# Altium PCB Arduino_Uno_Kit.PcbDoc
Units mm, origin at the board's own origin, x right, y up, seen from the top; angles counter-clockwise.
Board outline 142.1 x 65.4 mm, 2 copper layers (TOP, BOTTOM), stack 1.6 mm thick; 43 components, 40 nets, 248 pads, 2 vias.
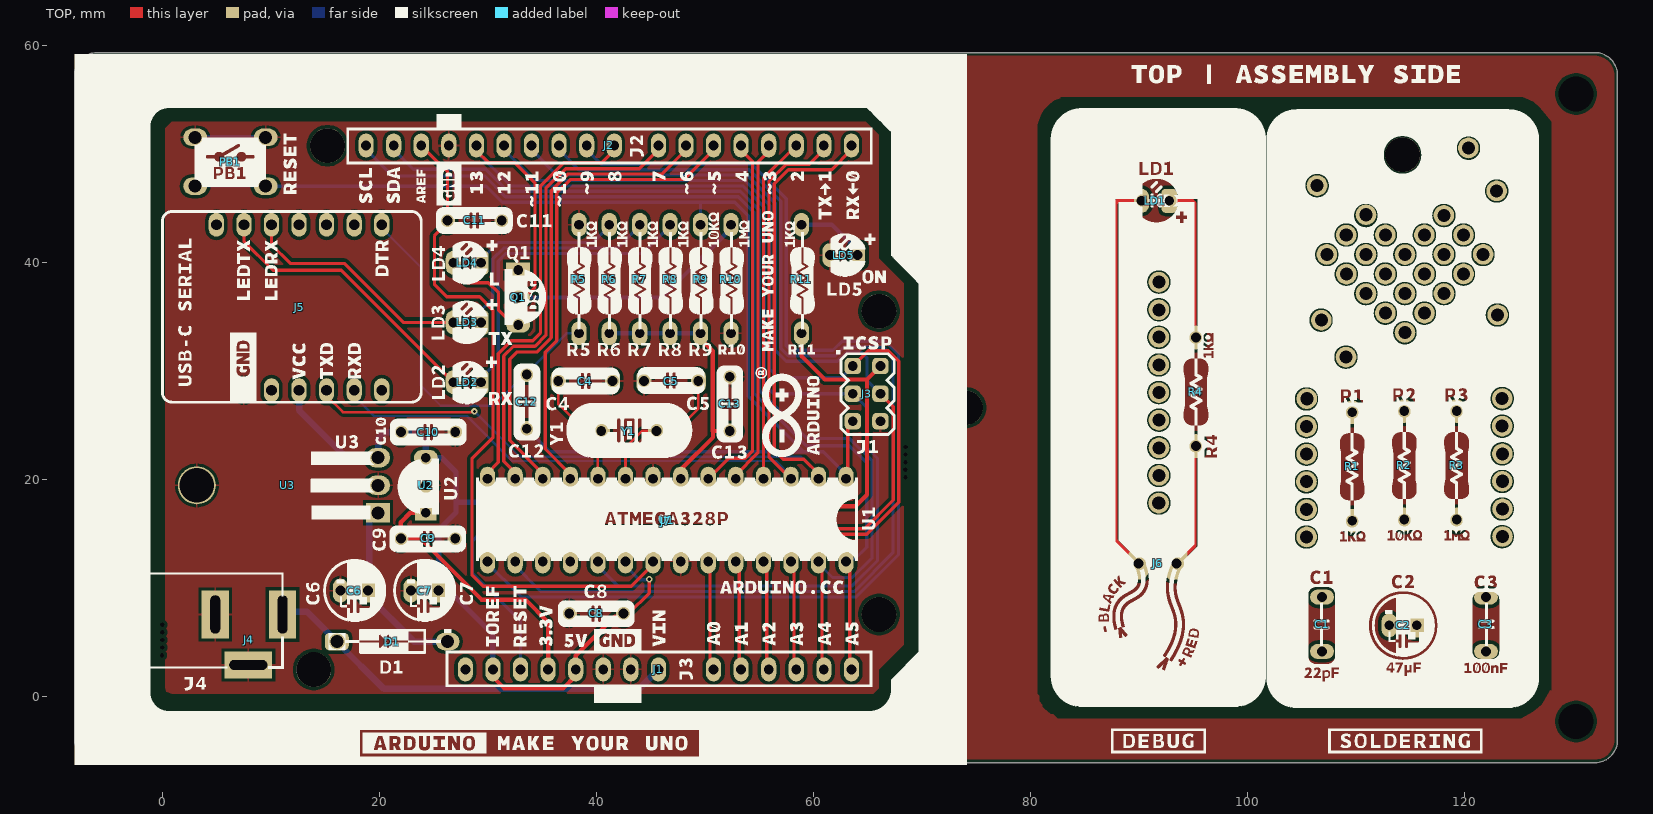
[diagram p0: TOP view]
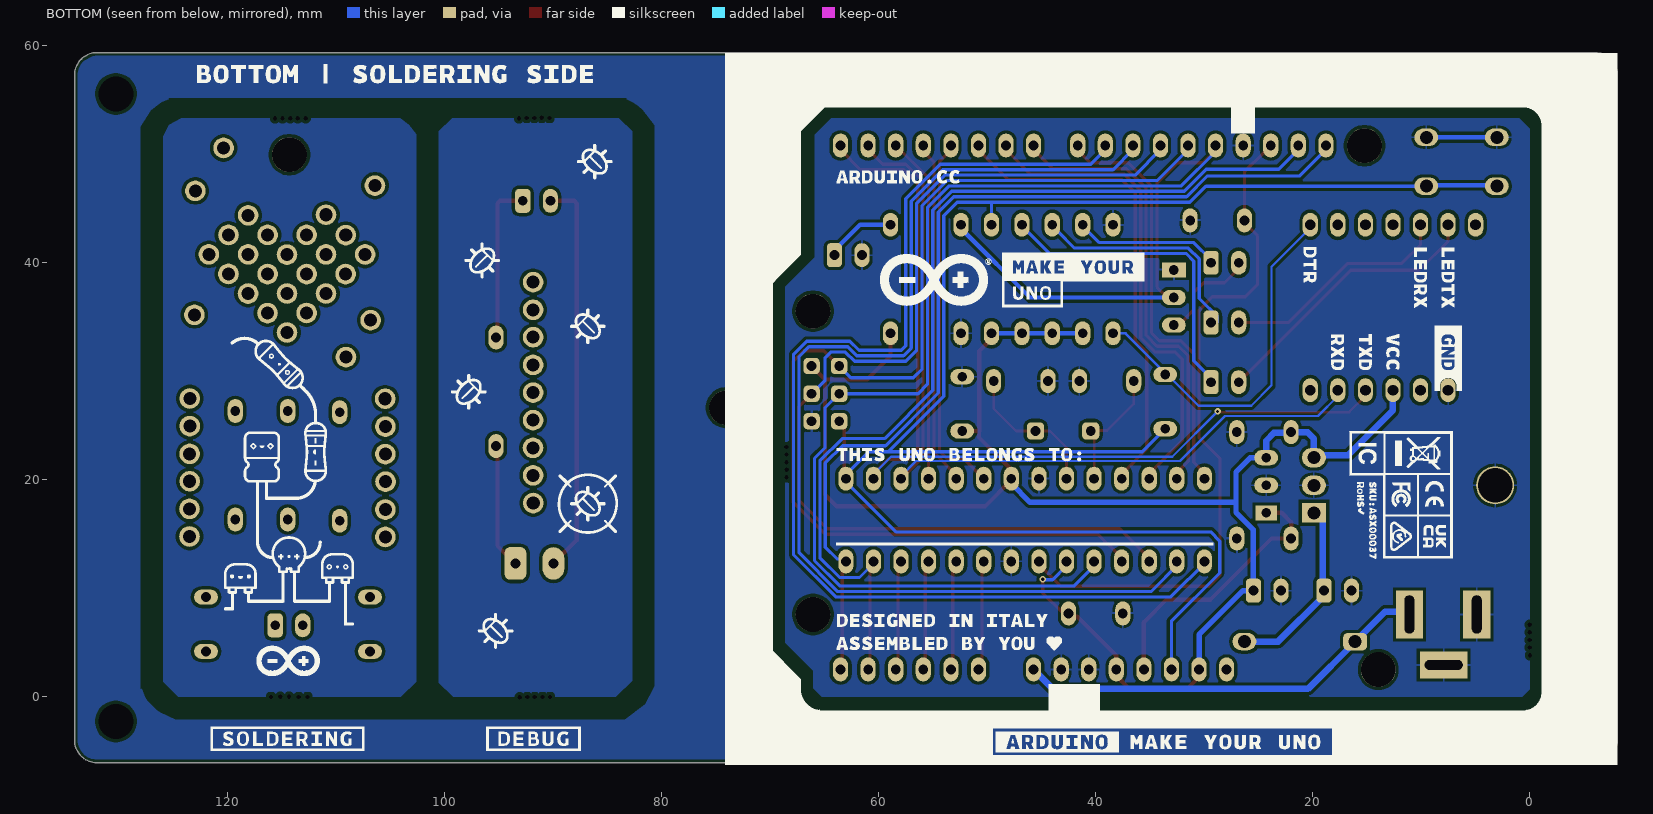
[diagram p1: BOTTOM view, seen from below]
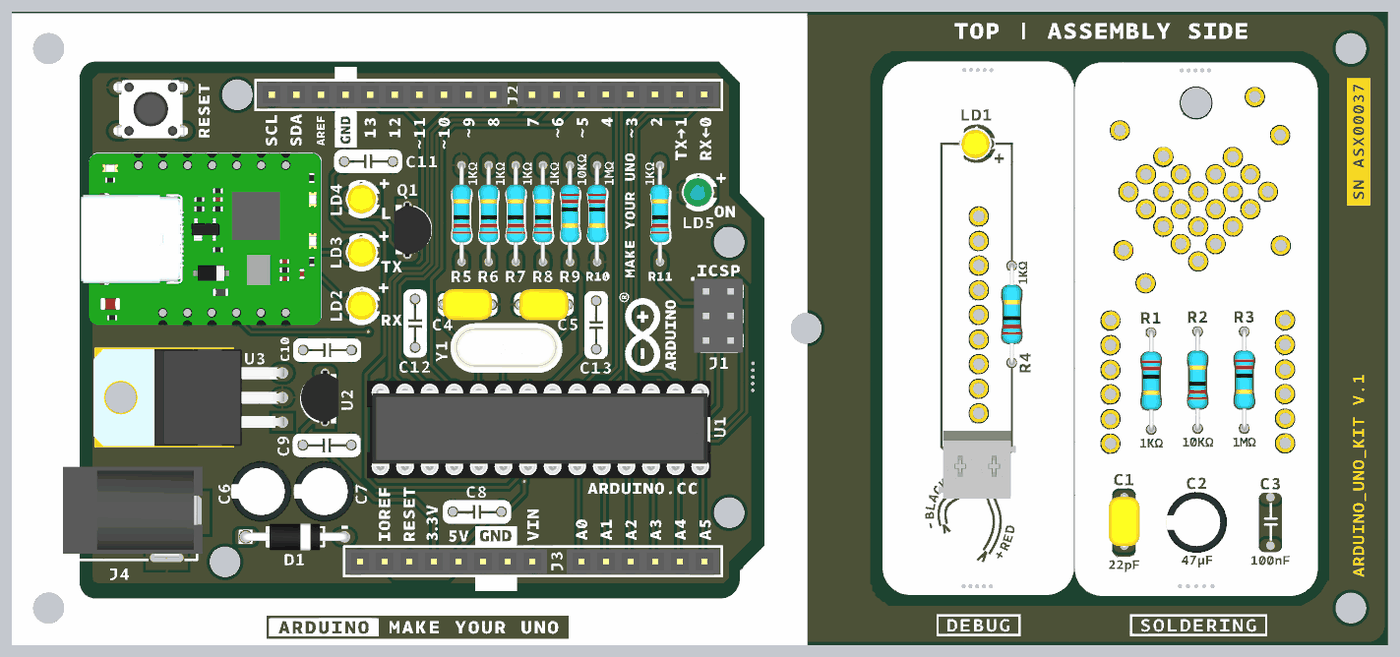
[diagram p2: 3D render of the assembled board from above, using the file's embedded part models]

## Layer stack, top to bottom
Top Solder: solder mask 0.0102, Solder Resist, Dk 3.5
TOP: signal copper 0.018
Dielectric2: core 1.564, FR-4, Dk 4.8
BOTTOM: signal copper 0.018
Bottom Solder: solder mask 0.0102, Solder Resist, Dk 3.5

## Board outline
-8.05,-3.999 -8.05,57.266 -8.05,57.3 cw(c-6,57.3) -6.02,59.35 -6.017,59.35 131.983,59.35 132,59.35 cw(c132,57.3) 134.05,57.3 134.05,-3.996 134.05,-4 cw(c132,-4) 132.029,-6.05 131.999,-6.05 -6,-6.05 cw(c-6,-4)

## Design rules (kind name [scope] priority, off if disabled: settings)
BoardOutlineClearance Silks [(OnLayer('Top Overlay') OR OnLayer('Bottom Overlay'))] p1: gap=0.1 ignorepadtopadclearanceinfootprint=FALSE
BoardOutlineClearance [All] p2: gap=0.3 ignorepadtopadclearanceinfootprint=FALSE
Clearance COPPER_0.3mm [All] p1: gap=0.127 ignorepadtopadclearanceinfootprint=FALSE except(0.2: Arc-Arc Arc-Track Track-Track; 0.3: Arc-Fill Arc-Poly Arc-Region Track-Fill Track-Poly Track-Region SMDPad-Fill SMDPad-Poly SMDPad-Region THPad-Fill THPad-Poly THPad-Region Via-Fill Via-Poly Via-Region Fill-Fill Fill-Poly Fill-Region Poly-Poly Poly-Region Region-Region)
Clearance "Generic clearance 0.127mm" [All] p2: gap=0.127 ignorepadtopadclearanceinfootprint=FALSE except(0.2: Arc-Arc Arc-Track Track-Track)
ComponentClearance [All] p1: gap=0.2 collisioncheckmode=3 verticalgap=0 showdistances=TRUE
DiffPairsRouting USB [InDifferentialPairClass('USB')] p1: maxlimit=0.15 minlimit=0.15 mostfreqgap=0.15 toplayer_minwidth=0.15 toplayer_maxwidth=0.21 toplayer_prefwidth=0.2 bottomlayer_minwidth=0.15 bottomlayer_maxwidth=0.21 bottomlayer_prefwidth=0.2 impedanceprofiledriven=TRUE impedanceprofileid={E6B00C31-4C8E-439C-824F-D2B2CDC26F9C} impedanceprofilevalue=90.000000 maxuncoupledlength=12.7
Height [All] p1: minheight=0 maxheight=30 prefheight=12.7
HoleSize [All] p1: absolutevalues=TRUE maxlimit=20 minlimit=0.3 maxpercent=80.000 minpercent=20.000
HoleToHoleClearance [All] p1: gap=0.2 allowstackedmicrovias=FALSE
MinimumAnnularRing [All] p1: minimumring=0.1
MinimumSolderMaskSliver [All] p1: minsoldermaskwidth=0.1
PlaneConnect [All] p1: pad.planeconnectstyle=Relief pad.reliefexpansion=0.508 pad.reliefentries=4 pad.reliefconductorwidth=0.254 pad.reliefairgap=0.254 via.planeconnectstyle=Direct via.reliefexpansion=0.508 via.reliefentries=4 via.reliefconductorwidth=0.254 via.reliefairgap=0.254
PolygonConnect [All] p1: thpad.connectstyle=Relief thpad.reliefconductorwidth=0.2 thpad.reliefentries=4 thpad.polygonreliefangle="90 Angle" thpad.airgapwidth=0.254 smdpad.connectstyle=Relief smdpad.reliefconductorwidth=0.2 smdpad.reliefentries=4 smdpad.polygonreliefangle="90 Angle" smdpad.airgapwidth=0.254 via.connectstyle=Direct via.reliefconductorwidth=0.254 via.reliefentries=4 via.polygonreliefangle="90 Angle" via.airgapwidth=0.254
RoomDefinition Aruino_Uno_Kit [InComponentClass('Aruino_Uno_Kit')] p1: confinementstyle=ConfineIn formatcopy=TRUE lockcomponents=FALSE outline -13.1,-11.6 148.5,-11.6 148.5,60.5 -13.1,60.5
RoutingVias StandardVias [All] p1: holewidth=0.3 width=0.6 viastyle="Through Hole" minholewidth=0.3 minwidth=0.6 maxholewidth=0.3 maxwidth=0.6
SMDToCorner [All] p1: distance=39370
SilkToSilkClearance [All] p1: silktosilkclearance=0.15
SilkToSolderMaskClearance [IsPad] p1: minsilkscreentomaskgap=0.1 clearancetoexposedcopper=TRUE
SolderMaskExpansion VIAtented [IsVia] p1: expansion=0.102 istentingtop=TRUE
SolderMaskExpansion [All] p2: expansion=0.05 istentingtop=FALSE
UnRoutedNet [All] p1: checkbadconnections=TRUE
ViasUnderSMD [All] p1: allowed=FALSE
Width StandardTraces [All] p1: maxlimit=5 minlimit=0.127 preferedwidth=0.4
20 further rules are at their usual default settings.

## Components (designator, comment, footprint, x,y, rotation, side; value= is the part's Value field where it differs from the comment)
C1 "TS170R1H220JSANB0R" TS170R1H220JSANB0R 106.85,6.7 r90 top value=22pF
C2 "EKF476M1EE05TU" EKF476M1EE05TU 114.307,6.597 r0 top value=47µF
C3 "B32529C0104J289" B32529C0104J289 121.947,6.7 r90 top value=100nF
C4 "TS170R1H220JSANB0R" TS170R1H220JSANB0R 39,29.1 r0 top value=22pF
C5 "TS170R1H220JSANB0R" TS170R1H220JSANB0R 46.9,29.1 r180 top value=22pF
C6 "EKF476M1EE05TU" EKF476M1EE05TU 17.7,9.8 r0 top value=47µF
C7 "EKF476M1EE05TU" EKF476M1EE05TU 24.2,9.8 r0 top value=47µF
C8 "B32529C0104J289" B32529C0104J289 40,7.7 r180 top value=100nF
C9 "B32529C0104J289" B32529C0104J289 24.5,14.6 r0 top value=100nF
C10 "B32529C0104J289" B32529C0104J289 24.5,24.4 r0 top value=100nF
C11 "B32529C0104J289" B32529C0104J289 28.8,43.9 r0 top value=100nF
C12 "B32529C0104J289" B32529C0104J289 33.6,27.2 r90 top value=100nF
C13 "B32529C0104J289" B32529C0104J289 52.3,27 r90 top value=100nF
D1 "1N4007G-T" 1N4007G-T-Footprint-1 21.1,5.1 r0 top
J1 "20TW-995" 1X14-CUSTOM 45.72,2.54 r0 top
J2 "20TW-994" 1X18-CUSTOM 45.72,50.8 r180 top
J3 "PH2-06-UA" 2X03 64.897,27.94 r90 top locked
J4 "19TW-746" POWERSUPPLY_DC-21MM 4.9,7.6 r0 top
J5 "USB-C Serial-Footprint (16U2)" "USB-C Serial-Footprint (16U2)" 11.92,35.88 r270 top
J6 "MK125002GO" MK125002GO 91.7,12.3 r180 top
J7 "ICS-328-T" ICS-328-T-Footprint-1 46.4,16.2 r180 top
LD1 "L-7104YD" L314YD-Footprint-1#1 91.5,45.7 r180 top
LD2 "L-7104YD" L314YD-Footprint-1#1 28.1,29 r180 top
LD3 "L-7104YD" L314YD-Footprint-1#1 28.1,34.5 r180 top
LD4 "L-7104YD" L314YD-Footprint-1#1 28.1,40 r180 top
LD5 "L-7104GD" L314YD-Footprint-1#2 62.8,40.7 r180 top
PB1 "TS21043-160B-5227260" SW6X6 6.3,49.3 r0 top
Q1 "2N7000BU" SOT23 32.8,36.8 r270 top
R1 "2-1623930-9" A5215 109.638,21.234 r270 top value=1K
R2 "0-1623930-3" A5213 114.422,21.343 r90 top value=10K
R3 "3-1623930-5" A5217 119.25,21.343 r270 top value=1M
R4 "2-1623930-9" A5215 95.235,28.111 r90 top value=1K
R5 "2-1623930-9" A5215 38.4,38.5 r90 top value=1K
R6 "2-1623930-9" A5215 41.2,38.5 r90 top value=1K
R7 "2-1623930-9" A5215 44,38.5 r90 top value=1K
R8 "2-1623930-9" A5215 46.8,38.5 r90 top value=1K
R9 "0-1623930-3" A5213 49.6,38.5 r270 top value=10k
R10 "3-1623930-5" A5217 52.4,38.5 r270 top value=1M
R11 "2-1623930-9" A5215 58.9,38.5 r90 top value=1K
U1 "ATMEGA328P-PU" DIL28-3 46.5,16.3 r180 top locked
U2 "LE33CZ" LE33CZ-TR/AP 24.3,19.5 r90 top
U3 "L7805ABP" TO220 19.9,19.5 r90 top
Y1 "ECS-160-20-4X-DU" ECS-160-20-4X-DU-Footprint-1 43,24.5 r180 top

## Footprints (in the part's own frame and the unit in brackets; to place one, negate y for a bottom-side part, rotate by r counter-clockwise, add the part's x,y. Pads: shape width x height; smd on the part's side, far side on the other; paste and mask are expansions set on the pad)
1N4007G-T-Footprint-1 [mm]
  rrect50% 2.2x1.6 hole 1.2 mask+0.05: 1(-5,0)
  oval 2.2x1.6 hole 1.2 mask+0.05: 2(5.2,0)
  body extent -5.43,-1.36 5.59,1.36, height 2.92
1X14-CUSTOM [mm]
  oval 1.4x2.2 hole 0.9 mask+0.05: 1(-17.78,0) 2(-15.24,0) 3(-12.7,0) 4(-10.16,0) 5(-7.62,0) 6(-5.08,0) 7(-2.54,0) 8(0,0) 9(5.08,0) 10(7.62,0) 11(10.16,0) 12(12.7,0) 13(15.24,0) 14(17.78,0)
  body extent -19.31,-1.27 19.29,1.27, height 8.5
1X18-CUSTOM [mm]
  oval 1.4x2.2 hole 0.9 mask+0.05: 1(-17.78,0) 2(-15.24,0) 3(-12.7,0) 4(-10.16,0) 5(-7.62,0) 6(-5.08,0) 7(-2.54,0) 8(0,0) 9(4.064,0) 10(6.604,0) 11(9.144,0) 12(11.684,0) 13(14.224,0) 14(16.764,0) 15(19.304,0) 16(21.844,0) 17(24.384,0) 18(26.924,0)
  body extent -19.26,-1.27 28.44,1.27, height 8.5
2X03 [mm]
  rrect50% 1.5x1.5 hole 0.9 mask+0.05: 1(2.54,1.27) 2(2.54,-1.27) 3(0,1.27) 4(0,-1.27) 5(-2.54,1.27) 6(-2.54,-1.27)
  body extent -3.81,-2.54 3.81,2.5, height 8.5
A5213 [mm] "Axial Resistor, 2-Leads, Dia 2.4mm, Body Length 6.3mm"
  oval 2.2x1.4 hole 0.9 mask+0.05: 1(-5,0) 2(5,0)
  body extent -5.23,-1 5.23,1, height 1.8
A5215 [mm] "Axial Resistor, 2-Leads, Dia 2.4mm, Body Length 6.3mm"
  oval 2.2x1.4 hole 0.9 mask+0.05: 1(-5,0) 2(5,0)
  body extent -5.22,-1 5.23,1, height 1.8
A5217 [mm] "Axial Resistor, 2-Leads, Dia 2.4mm, Body Length 6.3mm"
  oval 2.2x1.4 hole 0.9 mask+0.05: 1(-5,0) 2(5,0)
  body extent -5.22,-1 5.23,1, height 1.8
B32529C0104J289 [mm]
  oval 1.4x2.2 hole 0.9 mask+0.05: 1(-2.5,0) 2(2.5,0)
  body extent -3.56,-1.27 3.56,1.27, height 6.5
DIL28-3 [mm]
  oval 1.4x2.2 hole 0.9 mask+0.05: 1(-16.51,-3.81) 2(-13.97,-3.81) 3(-11.43,-3.81) 4(-8.89,-3.81) 5(-6.35,-3.81) 6(-3.81,-3.81) 7(-1.27,-3.81) 8(1.27,-3.81) 9(3.81,-3.81) 10(6.35,-3.81) 11(8.89,-3.81) 12(11.43,-3.81) 13(13.97,-3.81) 14(16.51,-3.81) 15(16.51,3.81) 16(13.97,3.81) 17(11.43,3.81) 18(8.89,3.81) 19(6.35,3.81) 20(3.81,3.81) 21(1.27,3.81) 22(-1.27,3.81) 23(-3.81,3.81) 24(-6.35,3.81) 25(-8.89,3.81) 26(-11.43,3.81) 27(-13.97,3.81) 28(-16.51,3.81)
  body extent -17.33,-3.95 17.32,3.95, height 7.04
ECS-160-20-4X-DU-Footprint-1 [mm]
  rrect50% 1.6x1.6 hole 0.9 mask+0.05: 1(-2.54,0) 2(2.54,0)
  body extent -5.75,-2.67 5.75,2.33, height 3.5
EKF476M1EE05TU [mm]
  oval 1.4x2.2 hole 0.9 mask+0.05: 1(-1.27,0)
  rrect50% 1.4x2.2 hole 0.9 mask+0.05: 2(1.27,0)
  body extent -3.15,-3.15 3.15,3.15, height 5.2
ICS-328-T-Footprint-1 [mm]
  body extent -17.75,-5.05 17.75,5.05, height 4.3
L314YD-Footprint-1#1 [mm]
  rrect50% 1.4x2.2 hole 0.9 mask+0.05: A(-1.27,0)
  oval 1.4x2.2 hole 0.9 mask+0.05: C(1.27,0)
  body extent -1.64,-1.65 1.66,1.65, height 6.31
L314YD-Footprint-1#2 [mm]
  rrect50% 1.4x2.2 hole 0.9 mask-1: A(-1.27,0)
  oval 1.4x2.2 hole 0.9 mask-1: C(1.27,0)
  body extent -1.66,-1.65 1.64,1.65, height 6.31
LE33CZ-TR/AP [mm] "TO, Thru-Hole, Vertical, Heatsink Mounted; 3 In-Line Leads; Pitch 2.54 mm"
  rect 1.4x2 hole 0.9 mask+0.05: 1(-2.54,0)
  oval 1.4x2.2 hole 0.9 mask+0.05: 2(0,0) 3(2.54,0)
  body extent -2.77,-1.37 2.77,2.5, height 9.3
MK125002GO [mm]
  rrect50% 2x3 hole 0.9: 1(-1.75,0)
  oval 2x3 hole 0.9: 2(1.75,0)
  body extent -3.95,-3.75 4.05,3.25, height 8.31
POWERSUPPLY_DC-21MM [mm]
  rect 2.5x4.4 hole 0.9 slot 3.5 at 90 deg mask+0.05: 1(6.2,0) 3(0,0)
  rect 4.4x2.5 hole 0.9 slot 3.5 at 0 deg mask+0.05: 2(3.05,-4.65)
  body extent -7.65,-4.65 6.75,4.75, height 3
SOT23 [mm]
  rect 1.4x2.2 hole 0.9 mask+0.05: 1(-2.54,0)
  oval 1.4x2.2 hole 0.9 mask+0.05: 2(0,0) 3(2.54,0)
  body extent -2.77,-1.37 2.77,2.5, height 8.5
SW6X6 [mm]
  oval 2.2x1.6 hole 1.2 mask+0.05: 1(-3.25,2.25) 2(3.25,2.25) 3(-3.25,-2.25) 4(3.25,-2.25)
  body extent -4.11,-3 4.11,3, height 10
TO220 [mm] "TO, Thru-Hole, Vertical, Heatsink Mounted; 3 In-Line Leads; Pitch 2.54 mm"
  rect 1.8x2.2 hole 1.2 mask+0.05: 1(-2.54,0)
  oval 1.8x2.2 hole 1.2 mask+0.05: 2(0,0) 3(2.54,0)
  round 3.5 hole 3.2 unplated: 4(0,16.7)
  body extent -5,-0.2 5,19.5, height 4.5
TS170R1H220JSANB0R [mm]
  oval 1.4x2.2 hole 0.9 mask+0.05: 1(-2.5,0) 2(2.5,0)
  body extent -2.79,-1.59 2.79,1.6, height 9.81
"USB-C Serial-Footprint (16U2)" [mm] "Default PCB Component"
  oval 2.2x1.4 hole 1 mask+0.05: 1(-7.62,-6.92) 2(-7.62,-4.38) 3(-7.62,-1.84) 4(-7.62,0.7) 5(-7.62,3.24) 6(-7.62,5.78) 7(-7.62,8.32) 8(7.62,8.32) 9(7.62,5.78) 10(7.62,3.24) 11(7.62,0.7) 12(7.62,-1.84) 13(7.62,-4.38)
  body extent -8.89,-12.8 8.89,12, height 7.44

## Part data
C1 C4 C5: library part C0124-A.13, "CAP THD 22pF 50V C0G 5%", Manufacturer=Suntan, Package="P : 5.08 Ammo", Tolerance=5%, Voltage=50V
C2 C6 C7: library part C0125-A.8, "CAP ALUM POL THD 47uF 25V", Manufacturer=SAMXON, Package="6.3x5mm  P. 2.5mm", Tolerance=20%, Voltage=25V
C3 C8 C9 C10 C11 C12 C13: library part C0127-A.6, "CAP THD 100NF 63V POLIESTER", Manufacturer=EPCOS, Tolerance=5%, Voltage=63V
D1: library part D0054-A.4, "Diodes [1N4007]", Manufacturer=Panjit, Voltage Rating (DC)=1kV
J1: library part J0063-A.5, "CONN STRIP F/1/D 14v SER.NERA s1pin"
J2: library part J0035-A.8, "CONN STRIP F/1/D 18v SER.NERA s1pin"
J3: library part J0004-A.4, "CONN Header Through Hole 6 position 0.100\" (2.54mm)", Manufacturer="Adam Tech"
J4: library part J0236-A.3, "CONN PWR JACK 2.1X5.5MM SOLDER", Manufacturer=4UCON
J5: library part AF0006-A.8
J6: library part J0012-A.7, "CONN MORS.CS 2v p3,5 10A aLING.VER", Manufacturer=Adimpex, Manufacturer 2="4U CON", Manufacturer Part Number 2=19TW-974
J7: library part J0044-A.1, "CONN DIP 28 SOCKET", Manufacturer="Adam Tech"
LD1 LD2 LD3 LD4: library part L0021-A.7, "LED THD YELLOW DIFFUSED T-1, 3mm", Manufacturer=Kingbright
LD5: library part L0023-A.5, "LED THD GREEN DIFFUSED T-1, 3mm", Manufacturer=Kingbright
PB1: library part B0002-A.6, "PUSHBUTTON.6x6 CS Hatt0,7 NERO 160g"
Q1: library part T0035-A.6, "TRANSISTOR NMOS SMALL SIGNAL EFFECT 0.2A I(D) 1-ELEMENT", Drain to Source Breakdown Voltage=60V, Manufacturer=Onsemi
R1 R4 R5 R6 R7 R8 R11: library part R0221-A.13, "RES FIXED THD 1K OHM 1/4W 5%", Manufacturer="TE connectivity", Power=250mW, Tolerance=5%
R2 R9: library part R0226-A.10, "RES THD 10K 1/4W 5%", Manufacturer="TE connectivity", Power=250mW, Tolerance=5%
R3 R10: library part R0227-A.11, "RES THD 1M OHM 1/4w  5%", Manufacturer="TE Connectivity", Power=250mW, Tolerance=5%
U1: library part U0038-A.2, "IC MICROCONTROLLER ATMEGA328P-PU", Manufacturer=Microchip
U2: library part U0246-A.6, "IC REG LDO FIXED 3.3V, 0.2V DROPOUT TO-92-3", Case/Package=TO-92-3, Dropout Voltage=2V, Manufacturer=STMicroelectronics, Max Input Voltage=18V, Max Operating Temperature=125°C, Max Output Current=100mA, Min Operating Temperature="- 40 C", Nominal Output Voltage=3V3, Output Voltage=3v3, Part Number=LE33CZ-TR/AP, Power Supply Rejection Ratio (PSRR)=80db, Quiescent Current=1mA, Tolerance=1%
U3: library part U0239-A.4, "IC REG LINEAR 5V 1.5A TO220AB", Case/Package=TO-220FP, Dropout Voltage=2V, Manufacturer=STMicroelectronics, Max Input Voltage=25V, Max Operating Temperature=125°C, Max Output Current=1.5A, Min Input Voltage=7V, Min Operating Temperature=0°C, Min Output Voltage=5V, Package Quantity=1000, Power Supply Rejection Ratio (PSRR)=62dB, Quiescent Current=8mA, Tolerance=5%
Y1: library part X0004-A.3, "CRYSTAL 16.0000MHZ 20PF THD", Manufacturer=ECS

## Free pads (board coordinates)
  round 1.9 hole 1.2: 0(91.809,17.866) 0(91.815,35.666) 0(91.815,38.211) 0(91.816,33.139) 0(91.82,28.04) 0(91.822,20.418) 0(91.823,25.499) 0(91.824,30.589) 0(91.83,22.952) 0(105.413,19.833) 0(105.424,24.904) 0(105.429,17.266) 0(105.434,22.373) 0(105.434,14.74) 0(105.444,27.472) 0(106.388,47.105) 0(106.786,34.706) 0(107.294,40.761) 0(109.059,31.305) 0(109.08,42.547) 0(109.093,38.959) 0(110.897,40.773) 0(110.9,37.166) 0(110.9,44.42) 0(112.679,38.959) 0(112.688,42.565) 0(112.689,35.371) 0(114.489,37.166) 0(114.49,33.573) 0(114.493,40.748) 0(116.278,38.96) 0(116.281,42.562) 0(116.287,35.362) 0(118.068,44.369) 0(118.073,40.775) 0(118.079,37.16) 0(119.881,42.556) 0(119.883,38.964) 0(120.333,50.57) 0(121.693,40.769) 0(122.935,46.616) 0(123.019,35.198) 0(123.445,24.955) 0(123.447,27.494) 0(123.451,19.871) 0(123.455,22.395) 0(123.471,14.784) 0(123.471,17.327)
  round 0 hole 3.2 unplated: 22(-4.25,-2.25) 22(-4.25,55.55) 22(130.25,-2.25) 22(130.25,55.55)
  round 0 hole 0.4 unplated: MOUSEBITES(0,3.851) MOUSEBITES(0.011,6.651) MOUSEBITES(0.013,4.551) MOUSEBITES(0.013,5.251) MOUSEBITES(0.017,5.951) MOUSEBITES(68.472,20.931) MOUSEBITES(68.476,21.631) MOUSEBITES(68.476,22.331) MOUSEBITES(68.478,20.231) MOUSEBITES(68.489,23.031) MOUSEBITES(90.259,-0.002) MOUSEBITES(90.317,53.333) MOUSEBITES(90.959,0.004) MOUSEBITES(91.017,53.339) MOUSEBITES(91.659,-0.001) MOUSEBITES(91.717,53.335) MOUSEBITES(92.359,-0.001) MOUSEBITES(92.417,53.335) MOUSEBITES(93.059,-0.013) MOUSEBITES(93.117,53.322) MOUSEBITES(112.6,0) MOUSEBITES(112.775,53.3) MOUSEBITES(113.42,0) MOUSEBITES(113.5,53.3) MOUSEBITES(114.2,53.3) MOUSEBITES(114.3,0.013) MOUSEBITES(114.9,53.3) MOUSEBITES(115.1,0.013) MOUSEBITES(115.6,53.3) MOUSEBITES(115.96,0)
  round 3.2 hole 3.2 unplated: ""(13.969,2.522) ""(15.239,50.782) ""(66.039,7.602) ""(66.039,35.542) ""(74,26.65) ""(114.27,49.953)

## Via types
v1: diameter 0.6, hole 0.3, TOP to BOTTOM, tented both sides, 2 vias

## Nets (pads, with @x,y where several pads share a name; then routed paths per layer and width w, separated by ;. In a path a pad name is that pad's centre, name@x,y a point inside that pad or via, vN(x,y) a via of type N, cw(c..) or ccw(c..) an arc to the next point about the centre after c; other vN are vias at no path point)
+3V3: C9.1 J1.4 U2.1 | length 25
  TOP w0.4: C9.1 22,16.103 22.857,16.96 U2.1@24.5,16.96 ; C9.1@22.5,14.6 23.8,14.6 29.43,8.97 33.469,8.97 35.56,6.879 J1.4
+5V: C7.2 C8.1 C10.1 C13.1 J1.2 J1.5 J3.2 J5.11 R6.1 R7.1 R8.1 R9.2 R11.1 U1.7 U1.20 U2.3 U3.3 | length 156.1
  TOP w0.3: C8.1 43,7.7 44.871,9.571 v1(44.871,10.838)
  TOP w0.4: J1.2 30.48,1.836 31.499,0.817 36.968,0.817 38.1,1.95 J1.5 38.1,3.817 41.7,7.417 42.217,7.417 C8.1 ; R9.2 49.6,33 50.727,31.873 50.727,24.5 50.743,24.5 ; C13.1 50.743,24.5 ; R11.1 58.9,31.4 61.054,29.246 64.933,29.246 ; J3.2 64.933,29.246 ; 50.743,24.5 50.743,23.914 47.961,21.132 47.961,20.172 47.77,19.981 50.197,17.553 63.853,17.553 64.933,18.633 64.933,29.246
  BOTTOM w0.3: U1.20 42.69,12.09 43.971,10.809 44.842,10.809 v1(44.871,10.838)
  BOTTOM w0.4: R6.1@40.9,33.498 R7.1@43.7,33.498 ; R7.1@43.7,33.5 R7.1 R8.1 R9.2@49.3,33.5
  BOTTOM w0.5: U2.3 25.76,22.04 27.078,20.722 27.078,17.936 ; C7.2 25.47,15.391 27.078,16.999 27.078,17.936 ; C7.2@25.8,9.8 26.42,9.8 30.48,5.74 J1.2 ; U1.7@47.77,20.57 U1.7 47.77,19.67 46.036,17.936 27.078,17.936
  BOTTOM w0.6: J5.11 12.62,26.404 16.754,22.27 19.67,22.27 U3.3 19.9,22.27 19.9,23.796 20.471,24.367 C10.1@22.033,24.367 ; C10.1@22,24.216 C10.1 22.071,24.329 23.584,24.329 24.3,23.613 U2.3
AD0: J1.9 U1.23 | length 10.2
  TOP w0.3: U1.23 50.478,12.322 50.478,3.56 50.8,3.238 J1.9
AD1: J1.10 U1.24 | length 10.2
  TOP w0.3: U1.24 52.85,11.897 53.161,11.587 53.161,2.719 J1.10
AD2: J1.11 U1.25 | length 10.2
  TOP w0.3: U1.25 55.39,11.897 55.701,11.586 55.701,2.719 J1.11
AD3: J1.12 U1.26 | length 10.2
  TOP w0.3: U1.26 57.93,11.897 58.216,11.611 58.216,2.744 J1.12
AD4/SDA: J1.13 J2.17 U1.27 | length 91.6
  TOP w0.3: U1.27 60.47,11.897 60.796,11.572 60.796,2.704 J1.13
  BOTTOM w0.3: J2.17 21.336,50.4 23.136,48.6 29.807,48.6 31.833,46.574 53.272,46.574 54.999,44.846 54.999,28.247 59.446,23.8 63.363,23.8 65.4,21.763 65.4,12.816 63.587,11.003 61.757,11.003 U1.27@60.27,12.49
AD5/SCL: J1.14 J2.18 U1.28 | length 88.5
  TOP w0.3: U1.28 63.01,11.897 63.351,11.557 63.351,2.689 J1.14
  BOTTOM w0.3: J2.18 18.796,50.4 21.196,48 29.7,48 31.626,46.074 53.064,46.074 54.499,44.639 54.499,28.001 59.355,23.145 63.31,23.145 64.9,21.556 64.9,13.8 63.81,12.71 63.23,12.71 U1.28
AREF: C11.1 J2.16 U1.21 | length 64.1
  TOP w0.3: J2.16 23.876,50.698 24.384,50.19 24.486,50.19 26.3,48.376 26.3,43.68 26.09,43.47 25.926,43.306 25.089,42.469 25.089,38.011 26.225,36.875 29.245,36.875 30.478,35.641 30.478,23.878 28.543,21.943 28.543,11.257 29.598,10.202 43.218,10.202 45.23,12.215 U1.21
DTR: C12.2 J5.7 R5.1 | length 34.4
  BOTTOM w0.2: J5.7@20.67,42.762 23.8,39.632 23.8,28.7 25.673,26.827 30.527,26.827 C12.2@33.4,29.7
  BOTTOM w0.25: C12.2@33.4,29.7 C12.2 ; C12.2@34.22,30.231 33.689,29.7 C12.2 ; R5.1 37.261,33.5 33.6,29.839 C12.2
GND: C4.2 C5.2 C6.1 C7.1 C8.2 C9.2 C10.2 C11.2 C13.2 J1.6 J1.7 J2.15 J3.6 J4.2 J4.3 J5.13 LD5.C PB1.1 PB1.2 Q1.1 R5.2 R10.2 U1.8 U1.22 U2.2 U3.2 U3.4 | length 5.9
  BOTTOM w0.4: PB1.1 PB1.2@8.995,51.55
IO0: J2.1 J5.10 U1.2 | length 88
  TOP w0.25: J5.10 15.16,27.74 16.662,26.238 28.709,26.238 v1(28.771,26.3)
  TOP w0.3: U1.2 60.47,20.537 59.107,21.9 57.2,21.9 56.4,22.7 56.4,47.274 57.7,48.574 61.674,48.574 63.5,50.4 J2.1
  BOTTOM w0.2: v1@28.782,26.3 32.952,22.13 58.85,22.13 60.47,20.51 U1.2
IO1: J2.2 J5.9 U1.3 | length 79
  TOP w0.3: U1.3 55.9,22.14 55.9,47.481 57.493,49.074 59.631,49.074 60.96,50.402 J2.2
  BOTTOM w0.2: J5.9 17.7,27.7 19.526,25.874 28.082,25.874 32.226,21.73 56.546,21.73 57.93,20.346 U1.3
IO2: J2.3 U1.4 | length 31.9
  TOP w0.3: U1.4 55.39,47.77 J2.3
IO3: J2.4 U1.5 | length 31.9
  TOP w0.3: U1.5@52.78,20.18 52.78,20.373 54.89,22.483 54.89,49.259 55.88,50.249 J2.4
IO4: J2.5 U1.6 | length 33.7
  TOP w0.3: U1.6 52.2,22 53.7,22 54.39,22.69 54.39,49.31 53.34,50.36 J2.5
IO5: J2.6 U1.11 | length 44.2
  TOP w0.3: U1.11 37.61,20.522 35.288,22.844 35.288,31.762 36.357,32.83 36.357,46.438 37.583,47.664 48.064,47.664 50.8,50.4 J2.6
IO6: J2.7 U1.12 | length 44.8
  TOP w0.3: U1.12 35.07,20.577 32.016,23.631 32.016,31.116 32.669,31.769 34.522,31.769 35.857,33.104 35.857,46.645 37.376,48.164 46.027,48.164 48.26,50.397 J2.7
IO7: J2.8 U1.13 | length 42.2
  TOP w0.3: U1.13 32.53,20.666 31.478,21.717 31.478,31.413 32.375,32.309 34.054,32.309 34.355,32.309 35.357,33.311 35.357,33.612 35.357,46.852 37.169,48.664 43.964,48.664 45.72,50.42 J2.8
IO8: J2.9 U1.14 | length 38.7
  TOP w0.3: U1.14 29.99,20.624 30.978,21.613 30.978,31.62 32.167,32.809 34.148,32.809 34.857,33.518 34.857,47.059 36.998,49.2 40.5,49.2 41.656,50.356 J2.9
IO9: J2.10 U1.15 | length 105
  BOTTOM w0.3: U1.15@29.79,12.49 33.067,9.213 63.96,9.213 67.826,13.078 67.826,31.249 67.826,31.568 66.625,32.769 62.635,32.769 61.802,31.936 57.907,31.936 57.499,32.343 57.499,45.882 54.307,49.074 40.442,49.074 39.116,50.4 J2.10
MISO: J2.13 J3.1 U1.18 | length 101.4
  TOP w0.3: U1.18 37.61,12.816 39.794,15 64.927,15 67.864,17.936 67.864,30.926 66.901,31.888 65.035,31.888 J3.1
  BOTTOM w0.3: J2.13 31.496,50.4 34.322,47.574 53.686,47.574 55.999,45.26 55.999,30.193 56.793,29.4 62.547,29.4 J3.1
MOSI: J2.12 J3.4 U1.17 | length 96.8
  TOP w0.3: U1.17 35.07,12.77 37.8,15.5 64.72,15.5 67.364,18.143 67.364,26.743 J3.4
  BOTTOM w0.3: J2.12 34.036,50.4 36.362,48.074 53.893,48.074 56.499,45.467 56.499,31.929 57.503,30.926 62.206,30.926 63.049,31.769 64.404,31.769 64.928,31.245 64.928,29.179 J3.4
NetC4_1: C4.1 U1.10 Y1.2 | length 11.2
  TOP w0.25: C4.1@36.5,29.148 36.5,26.983 38.941,24.542 39.806,24.542 40.292,24.056 40.292,24 40.138,23.846 U1.10@40.138,20.122
NetC5_1: C5.1 U1.9 Y1.1 | length 13.6
  TOP w0.25: U1.9 42.69,22.974 44.216,24.5 Y1.1 47.329,24.5 49.4,26.571 C5.1
NetC6_2: C6.2 D1.2 U3.1 | length 17.2
  BOTTOM w0.6: U3.1 19.707,16.96 19.107,16.36 19.107,9.937 C6.2 18.97,9.33 23.2,5.1 D1.2
NetJ5_2: J5.2 LD2.C | length 26.2
  TOP w0.3: J5.2 7.54,41.99 10.22,39.31 16.52,39.31 LD2.C
NetJ5_3: J5.3 LD3.C | length 21.6
  TOP w0.3: J5.3 10.08,41.66 11.806,39.934 16.786,39.934 22.22,34.5 LD3.C
NetJ6_1: J6.1 R4.1 | length 12.9
  TOP w0.4: J6.1 93.45,12.589 J6.1@94.227,13.367 ; J6.1@93.485,12.302 95.1,13.917 R4.1@95.1,23.1
NetJ6_2: J6.2 LD1.C | length 36.6
  TOP w0.4: J6.2 89.95,12.367 89.036,13.281 88.969,13.281 87.8,14.45 87.8,45.466 88.034,45.7 LD1.C
NetLD1_A: LD1.A R4.2 | length 14.6
  TOP w0.4: LD1.A 94.866,45.7 95.1,45.466 R4.2@95.1,34.037 ; R4.2@95.165,33.052 R4.2@95.697,32.52
NetLD2_A: LD2.A R8.2 | length 29
  BOTTOM w0.3: LD2.A 29.37,29.37 30.971,30.971 30.971,40.142 31.681,40.852 44.266,40.852 46.5,43.087 R8.2@46.5,43.5
NetLD3_A: LD3.A R7.2 | length 20.9
  BOTTOM w0.3: LD3.A@28.77,34.5 28.77,35.004 30.471,36.706 30.471,40.35 31.474,41.352 41.952,41.352 43.498,42.898 R7.2@43.795,42.898
NetLD4_A: LD4.A R6.2 | length 13.4
  BOTTOM w0.3: LD4.A 29.37,40.251 30.971,41.852 39.652,41.852 40.9,43.1 R6.2@40.9,43.5
NetLD4_C: LD4.C Q1.3 | length 9.8
  TOP w0.3: LD4.C 26.83,39.47 28.135,38.165 30.057,38.165 31,37.222 31,35.622 Q1.3@32.362,34.26 ; Q1.3@32.111,34.26 Q1.3@32.362,34.26 ; Q1.3 32.7,34.26 Q1.3@32.362,34.26
NetLD5_A: LD5.A R11.2 | length 6.8
  BOTTOM w0.4: R11.2@58.6,43.5 61.7,43.5 63.87,41.33 LD5.A@63.87,40.7
RESET: C12.1 J1.3 J3.5 PB1.3 PB1.4 R9.1 U1.1 | length 165.9
  TOP w0.3: U1.1 63.169,20.269 63.169,24.942 J3.5
  BOTTOM w0.25: U1.1 U1.1@63.01,20.49
  BOTTOM w0.3: PB1.4 29.85,47.05 31.326,45.574 49.6,45.574 ; C12.1@33,24.7 33.8,24.7 C12.1 33.7,24.6 35.72,22.58 59.107,22.58 ; J1.3 33.02,6.972 28.571,11.421 28.571,14.363 29.409,15.2 58.4,15.2 63.01,19.81 U1.1 ; R9.1 49.6,45.574 ; 60.92,22.58 59.107,22.58 ; 61,22.5 U1.1@63.01,20.49 ; 49.6,45.574 52.757,45.574 53.999,44.332 53.999,27.701 59.107,22.593 59.107,22.58
  BOTTOM w0.4: PB1.3@3.1,47.15 PB1.4@8.85,47.15
SCK: J2.14 J3.3 Q1.2 R10.1 U1.19 | length 139.4
  TOP w0.3: J2.14 28.956,50.317 30.073,49.2 32.492,49.2 34.357,47.335 34.357,37.753 33.404,36.8 Q1.2@32.7,36.8
  BOTTOM w0.3: J2.14 28.956,50.244 32.126,47.074 53.479,47.074 55.499,45.053 55.499,28.801 56.36,27.94 J3.3 64.933,26.634 64.933,22.937 65.9,21.97 65.9,12.567 63.546,10.213 42.027,10.213 U1.19@39.95,12.29
  BOTTOM w0.4: Q1.2@32.7,36.8 46.045,36.8 52.1,42.855 R10.1@52.1,43.5
SS: J2.11 U1.16 | length 103.3
  BOTTOM w0.3: U1.16@32.33,12.29 34.907,9.713 63.753,9.713 67.326,13.285 67.326,31.361 66.418,32.269 62.842,32.269 62.009,31.436 57.7,31.436 56.999,32.136 56.999,45.675 54.1,48.574 38.402,48.574 36.576,50.4 J2.11
VIN: D1.1 J1.8 J4.1 | length 38.5
  BOTTOM w0.6: J4.1@10.87,7.867 13.333,7.867 D1.1@16.076,5.124 ; D1.1@16.1,5.096 20.45,0.746 43.926,0.746 J1.8
pads on no net: C1.1 C1.2 C2.1 C2.2 C3.1 C3.2 J1.1 J5.1 J5.4 J5.5 J5.6 J5.8 J5.12 R1.1 R1.2 R2.1 R2.2 R3.1 R3.2

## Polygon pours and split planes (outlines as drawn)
GND on BOTTOM "NONET_L-01_P-001" (solid, pour order 9): -0.1,55.2 -1.001,54.5 -1.3,54.222 -1.818,53.331 -1.945,52.755 -2,52.505 -2,-0.303 -0.988,-1.314 -0.428,-1.7 0.1,-1.9 0.591,-2.037 65.744,-1.937 66.743,-1.5 67.4,-0.8 67.611,-0.489 67.835,-0.097 68,0.6 68.04,0.64 68.04,1.64 70.6,4.2 70.6,38.6 68.1,41.1 68.1,52.5 65.7,54.9 65.6,54.9 65.4,55.1 65.222,55.1 65.222,55.101 65.123,55.2 83.4,55.2 83.695,55.2 83.482,55.159 83.184,55.069 82.536,54.718 82.088,54.425 81.7,54.1 80.6,52.673 80.6,0.979 81.509,-0.652 83.397,-2.1 124.739,-2.1 126.224,-1.393 126.528,-1.163 126.802,-0.899 127.354,-0.369 127.544,-0.081 128.001,1.058 128,0.9 128,-6.148 128.002,-6.15 -6.15,-6.15 -8.05,-4.25 -8.05,55.199
GND on BOTTOM "NONET_L-01_P-001" (solid, pour order 8): -6.443,59.25 132.101,59.25 132.101,59.149 133.349,58.503 134.05,57.2 134,57.15 134,-4.68 132.53,-6.15 128,-6.15 128,52.506 127.045,54.029 126.08,54.805 125.078,55.2 125.611,55.2 -8.05,55.2 -8.05,57.643
no net on BOTTOM "NONET_L-01_P-001" (solid, pour order 5): 124.251,53.322 125.324,52.691 125.9,51.673 125.9,1.4 124.5,0 104,0 102.6,1.4 102.6,51.856 103.275,52.691 104.066,53.322
no net on BOTTOM "NONET_L-01_P-001" (solid, pour order 4): 99.278,53.322 100.5,52.1 100.5,1.3 99.2,0 84.2,0 82.7,1.5 82.7,52.106 83.928,53.322
GND on BOTTOM "NONET_L-01_P-001" (solid, pour order 0): -0.001,0.932 -0.001,52.321 0.999,53.321 0.999,53.322 64.378,53.322 65.9,51.8 65.9,40.5 68.6,37.8 68.6,5 66,2.4 66,0.808 65.228,0.036 0.694,0.036 -0.002,0.731 -0.002,0.98
GND on TOP "NONET_L-01_P-001" (solid, pour order 7): -0.1,55.3 -1.001,54.6 -1.3,54.322 -1.818,53.431 -1.945,52.855 -2,52.605 -2,-0.4 -2,0.255 -1.411,-0.846 -1.531,-0.727 -1.392,-0.846 -1.3,-1 -0.5,-1.8 -0.9,-1.4 -0.2,-1.8 0.451,-2 0.1,-2.1 0.451,-2 0.2,-2 65.7,-2 66.867,-1.4 67.606,-0.54 67.696,-0.304 67.899,0.181 68.041,0.911 68.03,1.231 68.047,1.747 69.333,2.983 70.6,4.3 70.6,38.7 68.1,41.2 68.1,52.6 65.7,55 65.6,55 65.4,55.2 65.222,55.2 65.222,55.201 65.123,55.3 82.8,55.3 82.835,55.201 82.186,54.988 81.7,54.6 81.2,54.1 80.937,53.637 80.937,53.837 80.937,53.637 80.6,52.7 80.6,0.3 80.8,0.1 80.8,-0.4 81.1,-0.7 81.1,-0.9 81.4,-1.2 81.445,-1.2 81.845,-1.6 82.1,-1.6 82.5,-2 125.167,-2 126.294,-1.383 127.089,-0.696 127.303,-0.352 128,0.827 128,-6.048 128.002,-6.05 -6.15,-6.05 -8.05,-4.15 -8.05,55.299
GND on TOP "NONET_L-01_P-001" (solid, pour order 6): -6.443,59.35 132.101,59.35 132.101,59.249 133.349,58.603 134.05,57.3 134,57.25 134,-4.58 132.53,-6.05 128,-6.05 128,52.971 126.926,54.294 126.353,54.834 125.272,55.3 -8.05,55.3 -8.05,57.743
no net on TOP "NONET_L-01_P-001" (solid, pour order 3): 102.7,1.4 102.7,51.8 103.286,52.729 104.222,53.322 124.178,53.322 125.362,52.729 125.9,51.6 125.9,1.4 124.5,0 104.1,0
no net on TOP "NONET_L-01_P-001" (solid, pour order 2): 82.6,52.1 83.8,53.3 99.179,53.321 100.7,51.8 100.7,1.4 99.299,-0.001 84.101,-0.001 82.6,1.5
GND on TOP "NONET_L-01_P-001" (solid, pour order 1): 0.3,52.4 0.9,53 64.8,53 66,51.8 66,40.4 68.3,38.1 68.3,4.8 66,2.5 66,0.8 65.5,0.3 0.89,0.3 0.405,0.492 0.3,0.89

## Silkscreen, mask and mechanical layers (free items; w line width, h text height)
Top Overlay:
  drawing of 414 lines, arcs and shapes, not listed
Bottom Overlay:
  drawing of 210 lines, arcs and shapes, not listed
Top Solder:
  drawing of 27 lines, arcs and shapes, not listed
Bottom Solder:
  drawing of 26 lines, arcs and shapes, not listed
Top Designator:
  lines w0.254: 2.412,43.5 20.24,43.5 20.24,41 ; 5,40.46 5,43.512 ; 7.54,25.13 7.54,28.26 22.561,28.26 ; 20.24,25.6 20.24,28.26 ; 74.094,59.35 74.1,57.2 ; 79,58.2 79,59.1
  text "R5" at 37.6,37.945 h1.52
Route Tool Path:
  lines w0.254: -1,3.3 -1,3.8 ; -1,37 -0.42,37.58
  lines w2: -1,7.3 -1,52.283 ; 69.579,20.231 69.579,5.062 ; 69.583,23.031 69.583,38.221 69.583,38.238 67.039,40.782 67.039,51.798 ; 81.645,2 ccw(c84.645,2) 84.645,-1 90.199,-1 ; 81.645,51.312 cw(c84.645,51.312) 84.645,54.312 ; 81.645,1.8 81.645,51.312 ; 84.645,54.322 90.319,54.322 ; 93.08,-1 98.685,-1 ccw(c98.685,2) 101.685,2 ; 93.119,54.322 98.645,54.322 ; 98.645,54.312 cw(c98.645,51.312) 101.645,51.312 ; 101.63,51.312 cw(c104.63,51.312) 104.63,54.312 ; 101.645,52.312 101.682,1 ; 101.676,2 ccw(c104.676,2) 104.676,-1 ; 104.63,54.322 112.496,54.322 ; 104.9,-1 112.6,-1 ; 115.835,54.32 123.976,54.313 ; 115.96,-1 123.976,-1 ; 123.976,54.312 cw(c123.976,51.312) 126.976,51.312 ; 124.02,-1 ccw(c124.02,2) 127.02,2 ; 126.98,51.312 127.016,2 ; -1.001,52.322 ccw(c-0.001,52.322) -1,52.283 ; -1.001,52.322 ccw(c-0.001,52.322) -1,52.283 ; -1.001,52.322 cw(c0.999,52.322) 0.999,54.322 64.515,54.322 ; -1,3.3 -1,3.3 ; -1,3.3 -1,1.038 ccw(c-0.002,0.98) -1.002,0.98 ccw(c0.98,0.98) 0.98,-1.002 ; 0.98,-1.002 ccw(c0.98,-0.002) 1.038,-1 ; 0.98,-1.002 ccw(c0.98,-0.002) 1.038,-1 ; 1.038,-1 64.914,-1 ccw(c64.914,1.102) 67.016,1.092 67.033,2.101 69.286,4.355 ; 64.515,54.322 cw(c64.515,53.322) 65.222,54.029 ; 64.515,54.322 cw(c64.515,53.322) 65.222,54.029 ; 65.222,54.029 66.746,52.505 ; 66.746,52.505 cw(c66.039,51.798) 67.039,51.798 ; 66.746,52.505 cw(c66.039,51.798) 67.039,51.798 ; 69.286,4.355 ccw(c68.579,5.062) 69.579,5.062 ; 69.286,4.355 ccw(c68.579,5.062) 69.579,5.062 ; 69.286,38.535 cw(c68.579,37.828) 69.579,37.828 ccw(c68.579,37.828) 69.286,38.535
Board:
  lines w0.1: -8,-4.034 -8,57.266 ; -8,-4 ccw(c-6,-4) -6,-6 132.029,-6 ; -8,57.3 cw(c-6,57.3) -6,59.3 132,59.3 cw(c132,57.3) 134,57.3 134,-4.175 ; 132,-6 ccw(c132,-4) 134,-4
